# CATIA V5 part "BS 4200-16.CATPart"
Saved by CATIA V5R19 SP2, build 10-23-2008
Part number: BS 4200-16
Bounding box of the stored display mesh (mm): x -47.487 to 47.487, y -47.487 to 47.487, z 0 to 97
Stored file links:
  C:\Users\Bora\Desktop\3D Katı model\BS serisi\BS 4200\BS 4200-16.CATPart
  C:\Program Files\Dassault Systemes\B19\intel_a\reffiles\standard\MetricThickPitch.txt
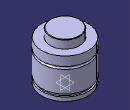
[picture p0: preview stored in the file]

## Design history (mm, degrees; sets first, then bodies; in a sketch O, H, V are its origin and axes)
Body1 (main body)
  Sketch1 on yz-plane, origin (0, 0, 0), H (0, 1, 0), V (0, 0, 1)
    point P2 (47.5, 56.5)
    point P5 (30, 96)
    point P7 (30, 96)
    point P11 (47.5, 61.5)
    point P13 (47.5, 61.5)
    point P14 (47.5, 56.5)
    line L1 (47.5, 13) -> (47.5, 56.5)
    line L2 (44.5, 13) -> (44.5, 8)
    line L3 (30, 96) -> (30, 80)
    arc A1 centre (29, 96) radius 1 from (30, 96) to (29, 97) ccw
    line L4 (47.5, 0) -> (47.5, 8)
    line L5 (47.5, 61.5) -> (47.5, 80)
    arc A2 centre (47.5, 59) radius 2.5 from (47.5, 61.5) to (47.5, 56.5) ccw
    line L6 (29, 97) -> (0, 97)
    point P15 (0, 97)
    line L7 (30, 80) -> (47.5, 80)
    line L8 (0, 0) -> (47.5, 0)
    line L9 (44.5, 13) -> (47.5, 13)
    line L10 (44.5, 8) -> (47.5, 8)
    coincidence: P15 V, P2 P14, P5 P7, P11 P13
    tangency: L6 A1
    horizontal: L7 H, L8 H, L9 H, L10 H
  Shaft1: profile Sketch1, axis Sketch1.V, angle 360
  Sketch2 on face of Shaft1 from Sketch1.L8, origin (0, 0, 0), H (1, 0, 0), V (0, -1, 0)
    point P1 (30, 0)
    distance P1 V = 30
  Hole1: placed by Sketch2, at (30, 0, 0) direction (0, 0, 1), diameter 6.647, depth 7, threaded "M8", thread diameter 8, thread depth 7, pitch 1.25
  CircPattern1: of Hole1, instances 4, angular step 90, axis from xy-plane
